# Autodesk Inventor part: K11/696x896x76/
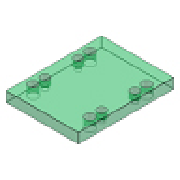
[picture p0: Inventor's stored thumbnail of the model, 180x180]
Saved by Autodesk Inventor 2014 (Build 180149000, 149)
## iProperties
Created: 2009-11
Part Number: K11/696x896x76/
Material: DIN 1.1730
Description: Top Clamping Plate
Document SubType Name: Modeling
Designer: gaom
Standard Revision: 1
Manufacturer: HASCO
Language: en-US
Size Designation: 696x896x76/
Categories: <MemberInstance><Categories><Category DisplayName="Mold" InternalName="349578f2-f4d4-4954-8c09-8e99297a61c0" Mnemonic="MOLD"><Category DisplayName="Mold Plates"
Density: 7.82 g/cm^3
Appearance: Clear - Green 1
IsCustomPart: 1
Author: gaom
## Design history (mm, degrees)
sketch "Sketch1"
  geometry: L1 (-398, 448)-(398, 448); L2 (398, 448)-(398, -448); L3 (398, -448)-(-398, -448); L4 (-398, -448)-(-398, 448); 3 further points
  constraints: 8 end point, 2 midpoint, 2 parallel, 1 horizontal, 1 horizontal alignment, 1 perpendicular, 1 vertical alignment
  dimensions: "d102" = 796 distance between parallel lines of L2 L4 (= W_); "d103" = 896 distance between parallel lines of L3 L1 (= L)
extrude "Extrusion1" new body sketch "Sketch1" distance "d20" = 76 (= H_); taper "d30" = 0 deg
sketch "Sketch2"
  geometry: 3 further points
  dimensions: "d72" = 296 horizontal distance of point (0, 0) point (-296, 337) (= 0.5 x S1_W); "d73" = 296 horizontal distance of point (0, 0) point (-296, 396) (= 0.5 x GP_W); "d74" = 396 vertical distance of point (0, 0) point (-296, 396) (= 0.5 x GP_L); "d75" = 337 vertical distance of point (0, 0) point (-296, 337) (= 0.5 x S1_L)
body "Solid1"
hole "Hole1" sketch "Sketch2" diameter "d76" = 54 (= GP_d1); stored, may be unused: countersink angle "d80" = 90 deg, drill point angle "d82" = 0 deg; dims "d77" = 6, "d78" = 4, "d79" = 2, "d81" = 76 (= H_)
hole "Hole2" sketch "Sketch2" diameter "d83" = 22 (= S1_d1); stored, may be unused: countersink angle "d87" = 90 deg, drill point angle "d89" = 0 deg; dims "d84" = 6, "d85" = 33 (= S1_d2), "d86" = 26 (= S1_k), "d88" = 76 (= H_)
pattern_linear "Rectangular Pattern1" dims "d92" = 674 (computed from S1_L, Ns), "d95" = 592 (computed from S1_W, Nw)
pattern_linear "Rectangular Pattern2" dims "d98" = 792 (computed from GP_L, Nl), "d101" = 592 (computed from GP_W, Nw)
chamfer "Chamfer1" distance "d104" = 0.5; stored, may be unused: second distance "d105" = 2, angle "d106" = 45 deg
other parameters: "L" = 896 [user parameter; used in 1 equation term], "W_" = 796 [user parameter; used in 1 equation term], "H_" = 76 [user parameter; used in 3 equation terms], "S1_W" = 592 [user parameter; used in 2 equation terms], "S1_d1" = 22 [user parameter; used in 1 equation term], "S1_d2" = 33 [user parameter; used in 1 equation term], "S1_k" = 26 [user parameter; used in 1 equation term], "S1_L" = 674 [user parameter; used in 2 equation terms], "GP_d1" = 54 [user parameter; used in 1 equation term], "GP_W" = 592 [user parameter; used in 2 equation terms], "GP_L" = 792 [user parameter; used in 2 equation terms], "M_W" = 696 [user parameter], "M_L" = 896 [user parameter]
